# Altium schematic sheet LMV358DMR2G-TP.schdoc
size 127 x 101 mm
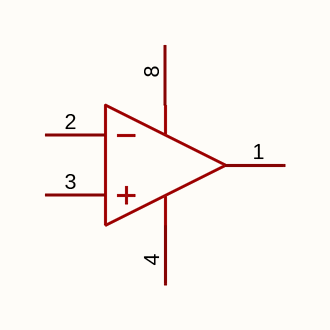
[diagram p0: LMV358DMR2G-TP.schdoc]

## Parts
U?  lmv358dmr2g-tp  [MSOP-8_L3.0-W3.0-P0.65-LS4.9-BL-1]  (value not drawn)  (part A of 2)

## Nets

Not connected (* = marked no-connect by the designer): U? 1(OUT1) 2(IN1-) 3(IN1+) 4(VEE) 8(VCC)

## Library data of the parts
U? = lmv358dmr2g-tp: 放大器数:2;轨到轨:轨到轨输入,轨到轨输出;增益带宽积(GBW):1MHz;输入失调电压(Vos):5mV;压摆率(SR):600V/ms;输入偏置电流(Ib):10pA;; Manufacturer: TECH PUBLIC(台舟); AddInBom: yes; ModelId: 374647af99ae41c4bb682bd336d5e4ed; ModelTransform: 118.11,192.913,0,0,0,0,0,0,0; Number of Channels: 2; Maximum Power Supply Range (Vdd-Vss): 5.5V; Gain Bandwidth Product: 1MHz; Vos - Input Offset Voltage: 5mV; Input Offset Voltage Drift(Vos TC): 2uV/℃; Ib - Input Bias Current: 10pA; Input Voltage Noise Density: 20nV/√Hz@10kHz; Common Mode Rejection Ratio(CMRR): 80dB; Quiescent Current: 80uA; Output Current: 20mA; Single supply: 2.5V~5.5V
